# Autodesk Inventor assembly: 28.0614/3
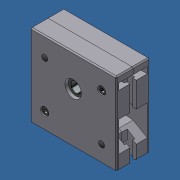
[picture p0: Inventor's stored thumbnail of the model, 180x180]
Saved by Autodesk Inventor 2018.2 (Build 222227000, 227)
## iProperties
Created: 2018-05
Part Number: 28.0614/3
Document SubType Name: Assembly
Designer: amoles
Description: TIMING BELT PULLEY T45 14mm
Stock Number: 28.0614 TIMING BELT PULLEY T45
Author: amoles
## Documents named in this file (12)
- Y:\INVENTOR LIBRARIES\PARTS LIBRARY\READY FOR USE MODULES LR\28.0614_3 TIMING BELT PULLEY T45 14mm.iam
- Y:\INVENTOR LIBRARIES\PARTS LIBRARY\READY FOR USE MODULES LR\SUBCOMPONENTS\28.0614 TIMING BELT PULLEY T45 RIGHT PLATE.ipt
- Y:\INVENTOR LIBRARIES\PARTS LIBRARY\READY FOR USE MODULES LR\SUBCOMPONENTS\SHIM DIN 988 - 25 x 35 x 0,1.ipt
- 00005263.ipt
- Y:\INVENTOR LIBRARIES\PARTS LIBRARY\READY FOR USE MODULES LR\Subcomponents\28.0083 BEARING.ipt
- Y:\INVENTOR LIBRARIES\PARTS LIBRARY\READY FOR USE MODULES LR\SUBCOMPONENTS\SHIM DIN 988 - 37 x 47 x 0,1.ipt
- 00005262.ipt
- Y:\INVENTOR LIBRARIES\PARTS LIBRARY\READY FOR USE MODULES LR\SUBCOMPONENTS\28.0614 TIMING BELT PULLEY T45 LEFT PLATE.ipt
- Y:\INVENTOR LIBRARIES\PARTS LIBRARY\FASTENING ELEMENTS\SCREWS CAP\M6X30 HIGH HEAD.ipt
- 00005264.ipt
- Y:\INVENTOR LIBRARIES\PARTS LIBRARY\END CAPS\22.1203 HOLE CAP M6.ipt
- Y:\INVENTOR LIBRARIES\PARTS LIBRARY\READY FOR USE MODULES LR\SUBCOMPONENTS\28.0047_2 T45 PULLEY 14mm.ipt
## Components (17 placed, 8 different names)
1. 28.0614 TIMING BELT PULLEY T45 RIGHT PLATE:1 — Flush:1, Flush:2, Flush:3, Mate:5, Mate:6, Mate:7, Angle:1, Insert:7, Insert:8, Insert:11, Insert:12, Angle:2
2. 28.0047_2 T45 PULLEY 14mm:1 — Insert:1, Insert:2, Mate:1, Mate:3, Mate:5, Mate:6, Mate:8, Angle:2
3. 00005263:1 — Insert:1, Insert:3
4. 00005263:2 — Insert:2, Insert:4
5. 28.0083 BEARING:1 — Insert:4, Mate:4
6. 28.0083 BEARING:2 — Insert:3, Mate:2
7. 00005262:1 — Mate:1, Mate:2
8. 00005262:2 — Mate:3, Mate:4
9. 28.0614 TIMING BELT PULLEY T45 LEFT PLATE:1 — Mate:7, Mate:8, Angle:1, Insert:5, Insert:6, Insert:9, Insert:10
10. 00005264:1 — Insert:6
11. 00005264:2 — Insert:5
12. 00005264:3 — Insert:8
13. 00005264:4 — Insert:7
14. 22.1203 HOLE CAP M6:1 — Insert:9
15. 22.1203 HOLE CAP M6:2 — Insert:10
16. 22.1203 HOLE CAP M6:3 — Insert:12
17. 22.1203 HOLE CAP M6:4 — Insert:11
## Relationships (25: Insert 12, Mate 8, Flush 3, Angle 2)
- Flush:1: 28.0614 TIMING BELT PULLEY T45 RIGHT PLATE:1
- Flush:2: 28.0614 TIMING BELT PULLEY T45 RIGHT PLATE:1
- Flush:3: 28.0614 TIMING BELT PULLEY T45 RIGHT PLATE:1
- Insert:1: 28.0047_2 T45 PULLEY 14mm:1 ↔ 00005263:1
- Insert:2: 28.0047_2 T45 PULLEY 14mm:1 ↔ 00005263:2
- Insert:3: 00005263:1 ↔ 28.0083 BEARING:2
- Insert:4: 00005263:2 ↔ 28.0083 BEARING:1
- Mate:1: 28.0047_2 T45 PULLEY 14mm:1 ↔ 00005262:1
- Mate:2: 28.0083 BEARING:2 ↔ 00005262:1
- Mate:3: 28.0047_2 T45 PULLEY 14mm:1 ↔ 00005262:2
- Mate:4: 28.0083 BEARING:1 ↔ 00005262:2
- Mate:5: 28.0614 TIMING BELT PULLEY T45 RIGHT PLATE:1 ↔ 28.0047_2 T45 PULLEY 14mm:1
- Mate:6: 28.0614 TIMING BELT PULLEY T45 RIGHT PLATE:1 ↔ 28.0047_2 T45 PULLEY 14mm:1
- Mate:7: 28.0614 TIMING BELT PULLEY T45 RIGHT PLATE:1 ↔ 28.0614 TIMING BELT PULLEY T45 LEFT PLATE:1
- Mate:8: 28.0047_2 T45 PULLEY 14mm:1 ↔ 28.0614 TIMING BELT PULLEY T45 LEFT PLATE:1
- Angle:1: 28.0614 TIMING BELT PULLEY T45 RIGHT PLATE:1 ↔ 28.0614 TIMING BELT PULLEY T45 LEFT PLATE:1
- Insert:5: 28.0614 TIMING BELT PULLEY T45 LEFT PLATE:1 ↔ 00005264:2
- Insert:6: 28.0614 TIMING BELT PULLEY T45 LEFT PLATE:1 ↔ 00005264:1
- Insert:7: 28.0614 TIMING BELT PULLEY T45 RIGHT PLATE:1 ↔ 00005264:4
- Insert:8: 28.0614 TIMING BELT PULLEY T45 RIGHT PLATE:1 ↔ 00005264:3
- Insert:9: 28.0614 TIMING BELT PULLEY T45 LEFT PLATE:1 ↔ 22.1203 HOLE CAP M6:1
- Insert:10: 28.0614 TIMING BELT PULLEY T45 LEFT PLATE:1 ↔ 22.1203 HOLE CAP M6:2
- Insert:11: 28.0614 TIMING BELT PULLEY T45 RIGHT PLATE:1 ↔ 22.1203 HOLE CAP M6:4
- Insert:12: 28.0614 TIMING BELT PULLEY T45 RIGHT PLATE:1 ↔ 22.1203 HOLE CAP M6:3
- Angle:2: 28.0614 TIMING BELT PULLEY T45 RIGHT PLATE:1 ↔ 28.0047_2 T45 PULLEY 14mm:1
